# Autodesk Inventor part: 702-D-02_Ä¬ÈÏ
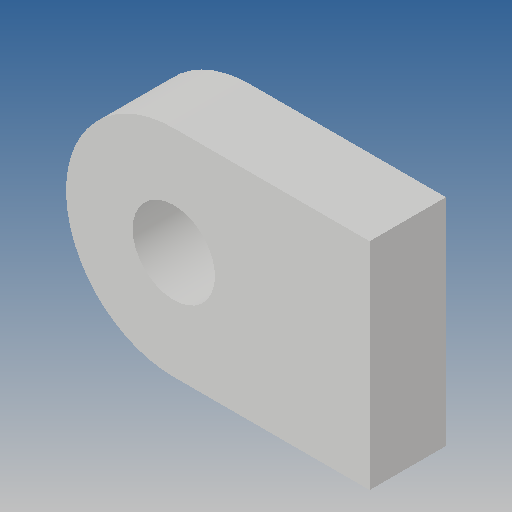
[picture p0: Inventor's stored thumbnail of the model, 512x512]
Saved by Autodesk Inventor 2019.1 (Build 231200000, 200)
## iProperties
Created: 2010-06
Part Number: 702-D-02_Ä¬ÈÏ
Material: Ogólny
Document SubType Name: Modeling
Designer: CADENGINEERING4
Density: 1 g/cm^3
Appearance: Domyślna
Author: CADENGINEERING4
Revision Number: ÈÎºÎ
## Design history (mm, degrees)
feature "NONE"
node "Bryła1"
